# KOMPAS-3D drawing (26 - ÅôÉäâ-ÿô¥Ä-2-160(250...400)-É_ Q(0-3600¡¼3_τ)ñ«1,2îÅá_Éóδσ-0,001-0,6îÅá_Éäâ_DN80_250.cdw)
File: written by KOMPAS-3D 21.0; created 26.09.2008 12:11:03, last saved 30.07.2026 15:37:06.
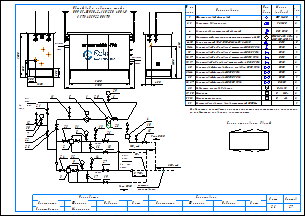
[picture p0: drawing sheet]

Sheets 1-2: A3, landscape

Document properties: Наименование: Макро:21; Автор: RaskoAdmin; Форматы листов документа: 2xA3; Полное имя файла: \\ur38nt01\Departments\КТО\КБ ПУРДГ\Заявки\Прайс-лист на типовые шкафы ГРПШ\ПУРДГ_стандарт_30_04_2026\ПУРДГ с РДГ(Н, В)\ПУРДГ-ШУЭО-2-160(250...400)-Р_ Q(0-3600нм3_ч)до1,2МПа_Рвых-0,001-0,6МПа_РДГ_DN80_250.cdw

Title block, sheet 1: Наименование: Пункт учета газа / ПУГ-Ш-400-Р / ЛГТИ.485922.001ТУ; designation: ЛГТИ.03.4411141; sheet number: 1; Количество листов документа: 2; organisation: ООО "ЭЛЬСТЕР Газэлектроника"; Форматы листов документа: A3; stored path: C:\Рабочие документы\Компас\ПУГ\Схема.cdw; Разработал: Устинов; Проверил: Кошкин; Утвердил: Кошкин
Title block, sheet 2: sheet number: 2; stored path: D:\Рабочие документы\Заявки\ПУРДГ\ПУРДГ-ШУЭО-2-100-Р 4411220.cdw; designation, second copy: ЛГТИ.03.4411141-

Views: Вид 1, Вид 2
Referenced files: wcvoit.frw
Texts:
  Normal
  № на
  схеме
  Усл.
  обозн.
  Марка
  (модель)
  Кол.
  Фильтр газовый фланцевый
  ФГ 16-80
  Регулятор давления газа
  РДГ-50
  Клапан предохранительный сбросной
  ПСК DN25
  Измерительный комплекс с ротационным счетчиком Ду50
  СГ-ЭК-Р-(0,2...2,0)-
  Кран кнопочный VE-РАСКО-НЗ-1,6-G1/2-М20
  DN15
  Кран шаровой "под приварку" штуцерный DN20 PN16
  Кран шаровой "под приварку" штуцерный DN25 PN16
  DN20
  DN25
  Кран шаровой "под приварку" штуцерный DN15 PN16
  Кран шаровой "под приварку" штуцерный п/п DN20 PN16
  Кран шаровой фланцевый с мех. приводом DN80 PN16
  Кран шаровой фланцевый DN50 PN16
  Кран шаровой фланцевый DN80 PN16
  Кран шаровой фланцевый DN250 PN16
  DN80
  DN50
  DN250
  Индикатор перепада давления
  Манометр
  Манометр-напоромер
  Электрообогреватель взрывозащищенный 2000Вт
  Delta 15
  0...     МПа
  0...     кПа
  Общий вид и габариты шкафа
  ПУРДГ-ШУЭО-2-160(250...400)-Р
  Выход газа
  Вход газа
  logo-rasko-ge.png
  DN 1
  местное
  сопротивление
  Римп DN20
  Выход
  газа
  Р=     кПа
  Вход
  Р=       МПа
  PDI
  Схема открывания дверей
  Предприятие изготовитель может заменять комплектующие на аналогичные,
  не ухудшающие заявленных характеристик.
  Должность
  Конструктор
  Фамилия
  Подпись
  Дата
  Согласовано
  Максимкин
  Лист
  Листов
  POLYLINE_STYLE_0.18_RGB_0_0_0
  POLYLINE_STYLE_0.50_RGB_0_0_0
  POLYLINE_STYLE_0.34_RGB_0_0_0
  PHANTOM_RGB_0_0_0_SC_1_THICK_0.18
  K5LT_THIN_RGB_0_0_0_THICK_0.18
  K5LT32769_RGB_0_0_0_THICK_0.18
  K5LT12_RGB_0_0_0_SC_1_THICK_0.18
  K5LT_DASHED_RGB_0_0_0_SC_1_THICK_0.18
  ACISOTGL_RGB_0_0_0_SC_0.8_THICK_0.25
  CONTINUOUS_RGB_0_127_31_THICK_0.3
  CONTINUOUS_RGB_0_0_255_THICK_0.35
  CONTINUOUS_RGB_255_0_0_THICK_0.35
  POLYLINE_STYLE_0.25_RGB_0_0_0
  CONTINUOUS_RGB_0_0_0_THICK_0.5
  POLYLINE_STYLE_0.35_RGB_0_0_255
  CONTINUOUS_RGB_0_0_0_THICK_0.4
  CONTINUOUS_RGB_0_0_0_THICK_0.35
  НЕВИДИМАЯ_RGB_0_0_0_SC_0.3_THICK_0.25
  СONTINUOUS_RGB_0_0_0_THICK_0.25
  ОСЕВАЯ2_RGB_248_153_30_SC_0.3_THICK_0.25
  Без оформления
Dimensions and other numbers on the sheet: 1; 2, 3; 2; 4; 5; -160 (250; 400)/1,6; 6-10; 11-14; 15; 16, 17; 18, 19; 20; 21-24; 25; 26, 27; 28; 29, 30; 31, 32; 33; 1500; 450; 500; 1200; 550; 305; 3600; 4130; 2000; 3900; 5,,,7DN 1; 7; 30; 12; 21; 22; 11; 6; 29; 23; 31; 8; 13; 26; 18; 10; 24; 32; 9; 3; 14; 27; 19; 16; 17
